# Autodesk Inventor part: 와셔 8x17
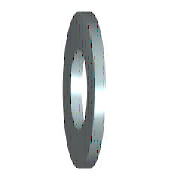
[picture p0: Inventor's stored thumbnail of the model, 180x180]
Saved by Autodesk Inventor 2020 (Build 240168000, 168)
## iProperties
Created: 2012-02
Part Number: 와셔 8x17
Material: 강철, 연강
Description: 평면 와셔
Document SubType Name: Modeling
Standard: KS B 1326
Designer: mduedu
Standards Organization: KS
Language: ko-KR
Size Designation: 8x17
Categories: <MemberInstance><Categories><Category DisplayName="조임쇠" InternalName="e4da775c-781d-43d5-af7c-5136215cf5a6" Mnemonic="FSTN"><Category DisplayName="와셔" InternalN
Density: 1 g/cm^3
Appearance: 주황색
IsCustomPart: 1
Author: mduedu
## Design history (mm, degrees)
sketch "스케치"
  geometry: C1 r 8.5 at (0, 0); C2 r 4.2 at (0, 0); 1 further point
  constraints: 2 centre point, 2 coincident
  dimensions: "d0" = 8.4 diameter of C2 (= SD1); "d1" = 17 diameter of C1 (= SD2)
extrude "본체" new body sketch "스케치" distance "d2" = 1.6 (= SD); taper "d3" = 0 deg
workaxis "Work Axis1"
workplane "Work Plane1"
body "Solid1"
other parameters: "SD1" = 8.4 [user parameter; used in 1 equation term], "SD2" = 17 [user parameter; used in 1 equation term], "SD" = 1.6 [user parameter; used in 1 equation term], "d4" = 0, "d5" = 0, "d6" = 0, "d7" = 0, "NND" = 8 [user parameter]
